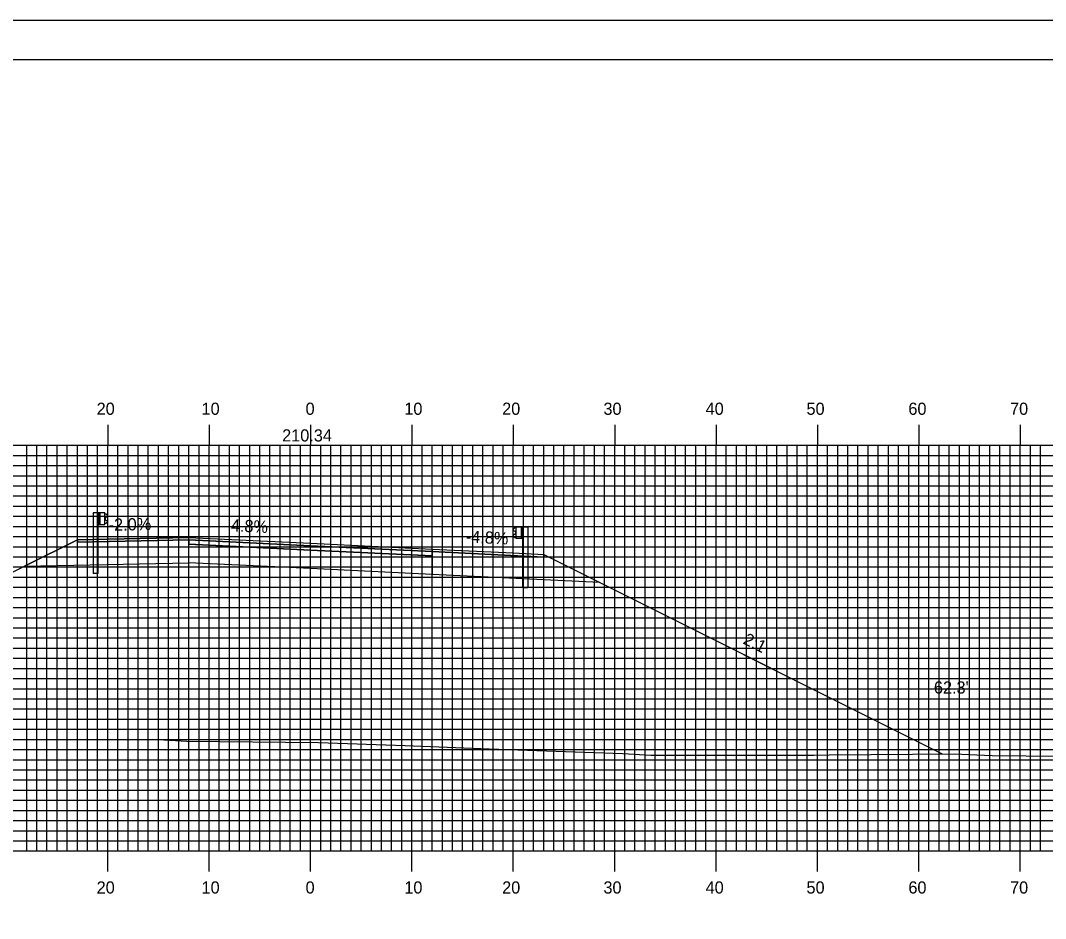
# Model space of a CAD drawing. Extents: x 1812948 to 1813291, y 442591 to 442811.
# Drawn here: x 1813084.9 to 1813186, y 442722 to 442810.5 of the extents above; entities that cross this region are included whole.
import ezdxf

# ---------------------------------------------------------------- set-up
doc = ezdxf.new("R2010")
doc.units = 0
for name, color, linetype in [('ANNOTATION', 7, 'Continuous'), ('BORDER', 7, 'Continuous'), ('D_Guardrail_Beam_Lt', 7, 'Continuous'), ('D_Guardrail_Beam_Rt', 7, 'Continuous'), ('D_Roadway_Centerline', 7, 'Continuous'), ('D_Roadway_Centerline_Text', 7, 'Continuous'), ('D_Roadway_Edge_Shoulder', 7, 'Continuous'), ('D_Roadway_Edge_TW', 7, 'Continuous'), ('D_Roadway_Pavement', 7, 'Continuous'), ('D_Roadway_SlopeLines', 7, 'Continuous'), ('D_Roadway_SubGrade', 7, 'Continuous'), ('D_Text_Standard', 7, 'Continuous'), ('H_V ANNOTATION', 7, 'Continuous'), ('MAJOR', 7, 'Continuous'), ('MINOR', 7, 'Continuous'), ('PLOT BOUNDARY', 7, 'Continuous'), ('S_Roadway_Centerline', 7, 'Continuous')]:
    doc.layers.add(name, color=color, linetype=linetype)

msp = doc.modelspace()

# ---------------------------------------------------------------- linework, layer by layer
at = {"layer": 'BORDER'}
msp.add_lwpolyline([(1812963.86, 442596.67), (1813283.86, 442596.67), (1813283.86, 442806.67), (1812963.86, 442806.67)], close=True, dxfattribs=at)
at = {"layer": 'D_Guardrail_Beam_Lt'}
for p, q in [((1813092.03, 442762.01), (1813092.03, 442756.01)), ((1813092.5, 442762.01), (1813092.03, 442762.01)), ((1813093.18, 442762.01), (1813092.5, 442762.01)), ((1813092.5, 442762.01), (1813092.5, 442760.84)), ((1813092.56, 442762.01), (1813092.56, 442760.84)), ((1813092.66, 442762.01), (1813092.66, 442760.84)), ((1813093.18, 442760.84), (1813093.18, 442762.01)), ((1813093.18, 442761.92), (1813093.26, 442761.91)), ((1813093.42, 442761.66), (1813093.22, 442761.52)), ((1813093.27, 442761.9), (1813093.42, 442761.8)), ((1813092.5, 442760.84), (1813093.18, 442760.84)), ((1813092.52, 442756.01), (1813092.52, 442760.84)), ((1813093.26, 442760.94), (1813093.18, 442760.92)), ((1813093.19, 442761.46), (1813093.19, 442761.39)), ((1813093.22, 442761.32), (1813093.42, 442761.19)), ((1813093.42, 442761.04), (1813093.27, 442760.94)), ((1813092.52, 442756.01), (1813092.03, 442756.01))]:
    msp.add_line(p, q, dxfattribs=at)
for centre, major_axis, start_param, end_param in [((1813093.25, 442761.87), (0.0417, 0), 0.959931, 1.376053), ((1813093.37, 442761.73), (0.0877, 0), 5.323254, 7.243116), ((1813093.27, 442761.46), (-0.0789, 0), 5.323254, 6.283185), ((1813093.27, 442761.39), (-0.0789, 0), 6.283185, 7.243116), ((1813093.25, 442760.98), (0.0417, 0), 4.907132, 5.323254), ((1813093.37, 442761.12), (0.0877, 0), 5.323254, 7.243116)]:
    msp.add_ellipse(centre, major_axis=major_axis, ratio=0.995501, start_param=start_param, end_param=end_param, dxfattribs=at)
at = {"layer": 'D_Guardrail_Beam_Rt'}
for p, q in [((1813133.73, 442760.63), (1813134.41, 442760.63)), ((1813133.73, 442759.46), (1813133.73, 442760.63)), ((1813134.25, 442760.63), (1813134.25, 442759.46)), ((1813134.35, 442760.63), (1813134.35, 442759.46)), ((1813134.41, 442760.63), (1813134.88, 442760.63)), ((1813134.41, 442760.63), (1813134.41, 442759.46)), ((1813134.88, 442760.63), (1813134.88, 442754.63)), ((1813133.64, 442760.53), (1813133.49, 442760.43)), ((1813133.49, 442760.28), (1813133.69, 442760.15)), ((1813133.69, 442759.95), (1813133.49, 442759.81)), ((1813133.49, 442759.67), (1813133.64, 442759.57)), ((1813133.73, 442760.55), (1813133.65, 442760.53)), ((1813133.72, 442760.08), (1813133.72, 442760.01)), ((1813133.65, 442759.56), (1813133.73, 442759.55)), ((1813134.41, 442759.46), (1813133.73, 442759.46)), ((1813134.39, 442754.63), (1813134.39, 442759.46)), ((1813134.39, 442754.63), (1813134.88, 442754.63))]:
    msp.add_line(p, q, dxfattribs=at)
for centre, major_axis, start_param, end_param in [((1813133.54, 442760.35), (-0.0877, 0), 5.323254, 7.243116), ((1813133.54, 442759.74), (-0.0877, 0), 5.323254, 7.243116), ((1813133.66, 442760.49), (-0.0417, 0), 4.907132, 5.323254), ((1813133.66, 442759.6), (-0.0417, 0), 0.959931, 1.376053), ((1813133.64, 442760.08), (0.0789, 0), 0, 0.959931), ((1813133.64, 442760.01), (0.0789, 0), 5.323254, 6.283185)]:
    msp.add_ellipse(centre, major_axis=major_axis, ratio=0.995501, start_param=start_param, end_param=end_param, dxfattribs=at)
at = {"layer": 'D_Roadway_Centerline'}
msp.add_lwpolyline([(1813056.1, 442742.18), (1813085.25, 442756.76), (1813090.46, 442759.36), (1813093.46, 442759.42), (1813101.46, 442759.58), (1813113.46, 442759.01), (1813125.46, 442758.43), (1813133.46, 442758.05), (1813136.46, 442757.9), (1813141.99, 442755.14), (1813175.76, 442738.25)], dxfattribs=at)
at = {"layer": 'D_Roadway_Edge_Shoulder'}
for points in [[(1813101.46, 442759.58), (1813093.46, 442759.42), (1813093.46, 442759.42), (1813090.46, 442759.36), (1813090.46, 442759.11), (1813101.46, 442759.33)], [(1813125.46, 442758.43), (1813133.46, 442758.05), (1813133.46, 442758.05), (1813136.46, 442757.9), (1813136.46, 442757.65), (1813125.46, 442758.18)]]:
    msp.add_lwpolyline(points, close=True, dxfattribs=at)
at = {"layer": 'D_Roadway_Edge_TW'}
msp.add_lwpolyline([(1813101.46, 442759.33), (1813101.46, 442759.58), (1813113.46, 442759.01), (1813125.46, 442758.43), (1813125.46, 442758.18), (1813113.46, 442758.76)], close=True, dxfattribs=at)
at = {"layer": 'D_Roadway_Pavement'}
msp.add_lwpolyline([(1813101.46, 442758.92), (1813101.46, 442759.33), (1813113.46, 442758.76), (1813125.46, 442758.18), (1813125.46, 442757.77), (1813113.46, 442758.34)], close=True, dxfattribs=at)
for points in [[(1813101.46, 442759.33), (1813101.46, 442758.92)], [(1813125.46, 442758.18), (1813125.46, 442757.77)]]:
    msp.add_lwpolyline(points, dxfattribs=at)
at = {"layer": 'D_Roadway_SlopeLines'}
for points in [[(1813090.46, 442759.36), (1813056.1, 442742.18)], [(1813136.46, 442757.9), (1813175.76, 442738.25)]]:
    msp.add_lwpolyline(points, dxfattribs=at)
at = {"layer": 'D_Roadway_SubGrade'}
for points in [[(1813101.46, 442758.92), (1813101.46, 442759.33), (1813090.46, 442759.11), (1813090.46, 442759.36), (1813085.25, 442756.76), (1813101.46, 442757.08)], [(1813101.46, 442757.08), (1813101.46, 442759.33), (1813101.46, 442758.92), (1813113.46, 442758.34), (1813125.46, 442757.77), (1813125.46, 442758.18), (1813125.46, 442755.93), (1813113.46, 442756.51)], [(1813125.46, 442757.77), (1813125.46, 442758.18), (1813136.46, 442757.65), (1813136.46, 442757.9), (1813141.99, 442755.14), (1813125.46, 442755.93)]]:
    msp.add_lwpolyline(points, close=True, dxfattribs=at)
at = {"layer": 'MAJOR'}
for p, q in [((1813093.46, 442770.67), (1813093.46, 442768.67)), ((1813103.46, 442770.67), (1813103.46, 442768.67)), ((1813113.46, 442770.67), (1813113.46, 442768.67)), ((1813123.46, 442770.67), (1813123.46, 442768.67)), ((1813133.46, 442770.67), (1813133.46, 442768.67)), ((1813143.46, 442770.67), (1813143.46, 442768.67)), ((1813153.46, 442770.67), (1813153.46, 442768.67)), ((1813163.46, 442770.67), (1813163.46, 442768.67)), ((1813173.46, 442770.67), (1813173.46, 442768.67)), ((1813183.46, 442770.67), (1813183.46, 442768.67)), ((1812973.46, 442768.67), (1813253.46, 442768.67)), ((1812973.46, 442768.67), (1813253.46, 442768.67)), ((1813093.46, 442728.67), (1813093.46, 442768.67)), ((1813103.46, 442728.67), (1813103.46, 442768.67)), ((1813113.46, 442728.67), (1813113.46, 442768.67)), ((1813123.46, 442728.67), (1813123.46, 442768.67)), ((1813133.46, 442728.67), (1813133.46, 442768.67)), ((1813143.46, 442728.67), (1813143.46, 442768.67)), ((1813153.46, 442728.67), (1813153.46, 442768.67)), ((1813163.46, 442728.67), (1813163.46, 442768.67)), ((1813173.46, 442728.67), (1813173.46, 442768.67)), ((1813183.46, 442728.67), (1813183.46, 442768.67)), ((1812973.46, 442763.67), (1813253.46, 442763.67)), ((1812973.46, 442758.67), (1813253.46, 442758.67)), ((1812973.46, 442753.67), (1813253.46, 442753.67)), ((1812973.46, 442748.67), (1813253.46, 442748.67)), ((1812973.46, 442743.67), (1813253.46, 442743.67)), ((1812973.46, 442738.67), (1813253.46, 442738.67)), ((1812973.46, 442733.67), (1813253.46, 442733.67)), ((1812973.46, 442728.67), (1813253.46, 442728.67)), ((1812973.46, 442728.67), (1813253.46, 442728.67)), ((1813093.46, 442726.66), (1813093.46, 442728.67)), ((1813103.46, 442726.66), (1813103.46, 442728.67)), ((1813113.46, 442726.66), (1813113.46, 442728.67)), ((1813123.46, 442726.66), (1813123.46, 442728.67)), ((1813133.46, 442726.66), (1813133.46, 442728.67)), ((1813143.46, 442726.66), (1813143.46, 442728.67)), ((1813153.46, 442726.66), (1813153.46, 442728.67)), ((1813163.46, 442726.66), (1813163.46, 442728.67)), ((1813173.46, 442726.66), (1813173.46, 442728.67)), ((1813183.46, 442726.66), (1813183.46, 442728.67))]:
    msp.add_line(p, q, dxfattribs=at)
at = {"layer": 'MINOR'}
for p, q in [((1813085.46, 442728.67), (1813085.46, 442768.67)), ((1813086.46, 442728.67), (1813086.46, 442768.67)), ((1813087.46, 442728.67), (1813087.46, 442768.67)), ((1813088.46, 442728.67), (1813088.46, 442768.67)), ((1813089.46, 442728.67), (1813089.46, 442768.67)), ((1813090.46, 442728.67), (1813090.46, 442768.67)), ((1813091.46, 442728.67), (1813091.46, 442768.67)), ((1813092.46, 442728.67), (1813092.46, 442768.67)), ((1813094.46, 442728.67), (1813094.46, 442768.67)), ((1813095.46, 442728.67), (1813095.46, 442768.67)), ((1813096.46, 442728.67), (1813096.46, 442768.67)), ((1813097.46, 442728.67), (1813097.46, 442768.67)), ((1813098.46, 442728.67), (1813098.46, 442768.67)), ((1813099.46, 442728.67), (1813099.46, 442768.67)), ((1813100.46, 442728.67), (1813100.46, 442768.67)), ((1813101.46, 442728.67), (1813101.46, 442768.67)), ((1813102.46, 442728.67), (1813102.46, 442768.67)), ((1813104.46, 442728.67), (1813104.46, 442768.67)), ((1813105.46, 442728.67), (1813105.46, 442768.67)), ((1813106.46, 442728.67), (1813106.46, 442768.67)), ((1813107.46, 442728.67), (1813107.46, 442768.67)), ((1813108.46, 442728.67), (1813108.46, 442768.67)), ((1813109.46, 442728.67), (1813109.46, 442768.67)), ((1813110.46, 442728.67), (1813110.46, 442768.67)), ((1813111.46, 442728.67), (1813111.46, 442768.67)), ((1813112.46, 442728.67), (1813112.46, 442768.67)), ((1813114.46, 442728.67), (1813114.46, 442768.67)), ((1813115.46, 442728.67), (1813115.46, 442768.67)), ((1813116.46, 442728.67), (1813116.46, 442768.67)), ((1813117.46, 442728.67), (1813117.46, 442768.67)), ((1813118.46, 442728.67), (1813118.46, 442768.67)), ((1813119.46, 442728.67), (1813119.46, 442768.67)), ((1813120.46, 442728.67), (1813120.46, 442768.67)), ((1813121.46, 442728.67), (1813121.46, 442768.67)), ((1813122.46, 442728.67), (1813122.46, 442768.67)), ((1813124.46, 442728.67), (1813124.46, 442768.67)), ((1813125.46, 442728.67), (1813125.46, 442768.67)), ((1813126.46, 442728.67), (1813126.46, 442768.67)), ((1813127.46, 442728.67), (1813127.46, 442768.67)), ((1813128.46, 442728.67), (1813128.46, 442768.67)), ((1813129.46, 442728.67), (1813129.46, 442768.67)), ((1813130.46, 442728.67), (1813130.46, 442768.67)), ((1813131.46, 442728.67), (1813131.46, 442768.67)), ((1813132.46, 442728.67), (1813132.46, 442768.67)), ((1813134.46, 442728.67), (1813134.46, 442768.67)), ((1813135.46, 442728.67), (1813135.46, 442768.67)), ((1813136.46, 442728.67), (1813136.46, 442768.67)), ((1813137.46, 442728.67), (1813137.46, 442768.67)), ((1813138.46, 442728.67), (1813138.46, 442768.67)), ((1813139.46, 442728.67), (1813139.46, 442768.67)), ((1813140.46, 442728.67), (1813140.46, 442768.67)), ((1813141.46, 442728.67), (1813141.46, 442768.67)), ((1813142.46, 442728.67), (1813142.46, 442768.67)), ((1813144.46, 442728.67), (1813144.46, 442768.67)), ((1813145.46, 442728.67), (1813145.46, 442768.67)), ((1813146.46, 442728.67), (1813146.46, 442768.67)), ((1813147.46, 442728.67), (1813147.46, 442768.67)), ((1813148.46, 442728.67), (1813148.46, 442768.67)), ((1813149.46, 442728.67), (1813149.46, 442768.67)), ((1813150.46, 442728.67), (1813150.46, 442768.67)), ((1813151.46, 442728.67), (1813151.46, 442768.67)), ((1813152.46, 442728.67), (1813152.46, 442768.67)), ((1813154.46, 442728.67), (1813154.46, 442768.67)), ((1813155.46, 442728.67), (1813155.46, 442768.67)), ((1813156.46, 442728.67), (1813156.46, 442768.67)), ((1813157.46, 442728.67), (1813157.46, 442768.67)), ((1813158.46, 442728.67), (1813158.46, 442768.67)), ((1813159.46, 442728.67), (1813159.46, 442768.67)), ((1813160.46, 442728.67), (1813160.46, 442768.67)), ((1813161.46, 442728.67), (1813161.46, 442768.67)), ((1813162.46, 442728.67), (1813162.46, 442768.67)), ((1813164.46, 442728.67), (1813164.46, 442768.67)), ((1813165.46, 442728.67), (1813165.46, 442768.67)), ((1813166.46, 442728.67), (1813166.46, 442768.67)), ((1813167.46, 442728.67), (1813167.46, 442768.67)), ((1813168.46, 442728.67), (1813168.46, 442768.67)), ((1813169.46, 442728.67), (1813169.46, 442768.67)), ((1813170.46, 442728.67), (1813170.46, 442768.67)), ((1813171.46, 442728.67), (1813171.46, 442768.67)), ((1813172.46, 442728.67), (1813172.46, 442768.67)), ((1813174.46, 442728.67), (1813174.46, 442768.67)), ((1813175.46, 442728.67), (1813175.46, 442768.67)), ((1813176.46, 442728.67), (1813176.46, 442768.67)), ((1813177.46, 442728.67), (1813177.46, 442768.67)), ((1813178.46, 442728.67), (1813178.46, 442768.67)), ((1813179.46, 442728.67), (1813179.46, 442768.67)), ((1813180.46, 442728.67), (1813180.46, 442768.67)), ((1813181.46, 442728.67), (1813181.46, 442768.67)), ((1813182.46, 442728.67), (1813182.46, 442768.67)), ((1813184.46, 442728.67), (1813184.46, 442768.67)), ((1813185.46, 442728.67), (1813185.46, 442768.67)), ((1812973.46, 442767.67), (1813253.46, 442767.67)), ((1812973.46, 442766.67), (1813253.46, 442766.67)), ((1812973.46, 442765.67), (1813253.46, 442765.67)), ((1812973.46, 442764.67), (1813253.46, 442764.67)), ((1812973.46, 442762.67), (1813253.46, 442762.67)), ((1812973.46, 442761.67), (1813253.46, 442761.67)), ((1812973.46, 442760.67), (1813253.46, 442760.67)), ((1812973.46, 442759.67), (1813253.46, 442759.67)), ((1812973.46, 442757.67), (1813253.46, 442757.67)), ((1812973.46, 442756.67), (1813253.46, 442756.67)), ((1812973.46, 442755.67), (1813253.46, 442755.67)), ((1812973.46, 442754.67), (1813253.46, 442754.67)), ((1812973.46, 442752.67), (1813253.46, 442752.67)), ((1812973.46, 442751.67), (1813253.46, 442751.67)), ((1812973.46, 442750.67), (1813253.46, 442750.67)), ((1812973.46, 442749.67), (1813253.46, 442749.67)), ((1812973.46, 442747.67), (1813253.46, 442747.67)), ((1812973.46, 442746.67), (1813253.46, 442746.67)), ((1812973.46, 442745.67), (1813253.46, 442745.67)), ((1812973.46, 442744.67), (1813253.46, 442744.67)), ((1812973.46, 442742.67), (1813253.46, 442742.67)), ((1812973.46, 442741.67), (1813253.46, 442741.67)), ((1812973.46, 442740.67), (1813253.46, 442740.67)), ((1812973.46, 442739.67), (1813253.46, 442739.67)), ((1812973.46, 442737.67), (1813253.46, 442737.67)), ((1812973.46, 442736.67), (1813253.46, 442736.67)), ((1812973.46, 442735.67), (1813253.46, 442735.67)), ((1812973.46, 442734.67), (1813253.46, 442734.67)), ((1812973.46, 442732.67), (1813253.46, 442732.67)), ((1812973.46, 442731.67), (1813253.46, 442731.67)), ((1812973.46, 442730.67), (1813253.46, 442730.67)), ((1812973.46, 442729.67), (1813253.46, 442729.67))]:
    msp.add_line(p, q, dxfattribs=at)
at = {"layer": 'PLOT BOUNDARY'}
msp.add_lwpolyline([(1812947.67, 442590.55), (1813287.67, 442590.55), (1813287.67, 442810.55), (1812947.67, 442810.55)], close=True, dxfattribs=at)
at = {"layer": 'S_Roadway_Centerline'}
msp.add_lwpolyline([(1813083.62, 442739.65), (1813095.98, 442739.66), (1813097.88, 442739.69), (1813101.27, 442739.51), (1813114.24, 442739.35), (1813122.8, 442739.07), (1813131.09, 442738.73), (1813144.26, 442738.29), (1813147.01, 442738.13), (1813156.22, 442738.12), (1813163.12, 442738.13), (1813164.63, 442738.16), (1813176.93, 442738.26), (1813180.7, 442738.09), (1813187.39, 442738.01), (1813199.2, 442737.83), (1813210.85, 442737.78), (1813217.43, 442737.68), (1813229.94, 442738.24), (1813232.32, 442738.32), (1813245.29, 442737.66), (1813248.44, 442737.56), (1813253.46, 442737.68)], dxfattribs=at)

# ---------------------------------------------------------------- texts
at = {"layer": 'ANNOTATION'}
for s, rotation, p in [('-2.0%', 1.1458, (1813093.56, 442760.23)), ('4.8%', 357.2519, (1813105.58, 442760.19)), ('-4.8%', 357.2519, (1813128.76, 442759.08)), ('2:1', 333.4349, (1813156.04, 442749.15))]:
    msp.add_text(s, height=1.2, rotation=rotation, dxfattribs=at).set_placement(p)
at = {"layer": 'D_Roadway_Centerline'}
for s, p in [('C', (1813113.45, 442759.01)), ('L', (1813113.46, 442759))]:
    msp.add_text(s, height=0.0146, dxfattribs=at).set_placement(p)
at = {"layer": 'D_Roadway_Centerline_Text'}
msp.add_text('210.34', height=1.2, dxfattribs=at).set_placement((1813110.66, 442769.04))
at = {"layer": 'D_Text_Standard'}
msp.add_text("62.3'", height=1.2, dxfattribs=at).set_placement((1813174.95, 442744.19))
at = {"layer": 'H_V ANNOTATION'}
for s, p in [('20', (1813092.36, 442771.67)), ('10', (1813102.71, 442771.67)), ('0', (1813112.97, 442771.67)), ('10', (1813122.71, 442771.67)), ('20', (1813132.36, 442771.67)), ('30', (1813142.35, 442771.67)), ('40', (1813152.43, 442771.67)), ('50', (1813162.38, 442771.67)), ('60', (1813172.43, 442771.67)), ('70', (1813182.46, 442771.67)), ('20', (1813092.36, 442724.47)), ('10', (1813102.71, 442724.47)), ('0', (1813112.97, 442724.47)), ('10', (1813122.71, 442724.47)), ('20', (1813132.36, 442724.47)), ('30', (1813142.35, 442724.47)), ('40', (1813152.43, 442724.47)), ('50', (1813162.38, 442724.47)), ('60', (1813172.43, 442724.47)), ('70', (1813182.46, 442724.47))]:
    msp.add_text(s, height=1.2, dxfattribs=at).set_placement(p)

doc.saveas('drawing.dxf')
